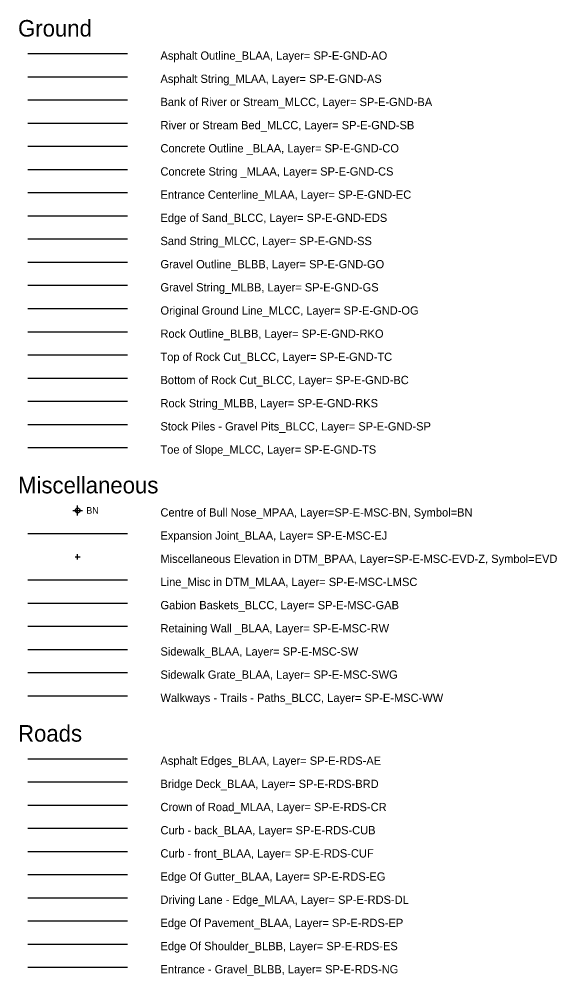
# Model space of a CAD drawing. Extents: x 500528 to 502626, y 4210261 to 4212624.
# Drawn here: x 501883.9 to 502046.2, y 4212035 to 4212324 of the extents above; entities that cross this region are included whole.
import ezdxf

# ---------------------------------------------------------------- set-up
doc = ezdxf.new("R2010")
doc.units = 0
for name, color, linetype in [('Default', 7, 'Continuous'), ('SP-E-GND-AO', 7, 'Continuous'), ('SP-E-GND-AS', 7, 'Continuous'), ('SP-E-GND-BA', 7, 'Continuous'), ('SP-E-GND-BC', 7, 'Continuous'), ('SP-E-GND-CO', 7, 'Continuous'), ('SP-E-GND-CS', 7, 'Continuous'), ('SP-E-GND-EC', 7, 'Continuous'), ('SP-E-GND-EDS', 7, 'Continuous'), ('SP-E-GND-GO', 7, 'Continuous'), ('SP-E-GND-GS', 7, 'Continuous'), ('SP-E-GND-OG', 7, 'Continuous'), ('SP-E-GND-RKO', 7, 'Continuous'), ('SP-E-GND-RKS', 7, 'Continuous'), ('SP-E-GND-SB', 7, 'Continuous'), ('SP-E-GND-SP', 7, 'Continuous'), ('SP-E-GND-SS', 7, 'Continuous'), ('SP-E-GND-TC', 7, 'Continuous'), ('SP-E-GND-TS', 7, 'Continuous'), ('SP-E-MSC-BN', 7, 'Continuous'), ('SP-E-MSC-EJ', 7, 'Continuous'), ('SP-E-MSC-EVD-Z', 7, 'Continuous'), ('SP-E-MSC-GAB', 7, 'Continuous'), ('SP-E-MSC-LMSC', 7, 'Continuous'), ('SP-E-MSC-RW', 7, 'Continuous'), ('SP-E-MSC-SW', 7, 'Continuous'), ('SP-E-MSC-SWG', 7, 'Continuous'), ('SP-E-MSC-T', 7, 'Continuous'), ('SP-E-MSC-WW', 7, 'Continuous'), ('SP-E-RDS-AE', 7, 'Continuous'), ('SP-E-RDS-BRD', 7, 'Continuous'), ('SP-E-RDS-CR', 7, 'Continuous'), ('SP-E-RDS-CUB', 7, 'Continuous'), ('SP-E-RDS-CUF', 7, 'Continuous'), ('SP-E-RDS-DL', 7, 'Continuous'), ('SP-E-RDS-EG', 7, 'Continuous'), ('SP-E-RDS-EP', 7, 'Continuous'), ('SP-E-RDS-ES', 7, 'Continuous'), ('SP-E-RDS-NG', 7, 'Continuous')]:
    doc.layers.add(name, color=color, linetype=linetype)

# ---------------------------------------------------------------- blocks, each defined once
blk = doc.blocks.new('POINT_DISPLAY')
at = {"layer": 'Default'}
blk.add_line((0, 0), (0, 0), dxfattribs=at)
blk = doc.blocks.new('BN')
at = {"layer": 'SP-E-MSC-T'}
for points in [[(-0.15, 0), (0.15, 0)], [(0, -0.15), (0, 0.15)]]:
    blk.add_lwpolyline(points, dxfattribs=at)
blk.add_circle((0, 0), 0.075, dxfattribs=at)
at = {"layer": 'SP-E-MSC-BN'}
blk.add_blockref('POINT_DISPLAY', (0, 0), dxfattribs=at)
at = {"layer": 'SP-E-MSC-T'}
blk.add_text('BN', height=0.2, dxfattribs=at).set_placement((0.262, -0.1))
blk = doc.blocks.new('EVD')
at = {"layer": 'SP-E-MSC-T'}
for points in [[(-0.08, 0), (0.08, 0)], [(0, -0.08), (0, 0.08)]]:
    blk.add_lwpolyline(points, dxfattribs=at)
at = {"layer": 'SP-E-MSC-EVD-Z'}
blk.add_blockref('POINT_DISPLAY', (0, 0), dxfattribs=at)

msp = doc.modelspace()

# ---------------------------------------------------------------- linework, layer by layer
at = {"layer": 'SP-E-GND-AO'}
msp.add_line((501886.55, 4212313.59), (501916.55, 4212313.59), dxfattribs=at)
at = {"layer": 'SP-E-GND-AS'}
msp.add_line((501886.55, 4212306.59), (501916.55, 4212306.59), dxfattribs=at)
at = {"layer": 'SP-E-GND-BA'}
msp.add_line((501886.55, 4212299.59), (501916.55, 4212299.59), dxfattribs=at)
at = {"layer": 'SP-E-GND-BC'}
msp.add_line((501886.55, 4212215.59), (501916.55, 4212215.59), dxfattribs=at)
at = {"layer": 'SP-E-GND-CO'}
msp.add_line((501886.55, 4212285.59), (501916.55, 4212285.59), dxfattribs=at)
at = {"layer": 'SP-E-GND-CS'}
msp.add_line((501886.55, 4212278.59), (501916.55, 4212278.59), dxfattribs=at)
at = {"layer": 'SP-E-GND-EC'}
msp.add_line((501886.55, 4212271.59), (501916.55, 4212271.59), dxfattribs=at)
at = {"layer": 'SP-E-GND-EDS'}
msp.add_line((501886.55, 4212264.59), (501916.55, 4212264.59), dxfattribs=at)
at = {"layer": 'SP-E-GND-GO'}
msp.add_line((501886.55, 4212250.59), (501916.55, 4212250.59), dxfattribs=at)
at = {"layer": 'SP-E-GND-GS'}
msp.add_line((501886.55, 4212243.59), (501916.55, 4212243.59), dxfattribs=at)
at = {"layer": 'SP-E-GND-OG'}
msp.add_line((501886.55, 4212236.59), (501916.55, 4212236.59), dxfattribs=at)
at = {"layer": 'SP-E-GND-RKO'}
msp.add_line((501886.55, 4212229.59), (501916.55, 4212229.59), dxfattribs=at)
at = {"layer": 'SP-E-GND-RKS'}
msp.add_line((501886.55, 4212208.59), (501916.55, 4212208.59), dxfattribs=at)
at = {"layer": 'SP-E-GND-SB'}
msp.add_line((501886.55, 4212292.59), (501916.55, 4212292.59), dxfattribs=at)
at = {"layer": 'SP-E-GND-SP'}
msp.add_line((501886.55, 4212201.59), (501916.55, 4212201.59), dxfattribs=at)
at = {"layer": 'SP-E-GND-SS'}
msp.add_line((501886.55, 4212257.59), (501916.55, 4212257.59), dxfattribs=at)
at = {"layer": 'SP-E-GND-TC'}
msp.add_line((501886.55, 4212222.59), (501916.55, 4212222.59), dxfattribs=at)
at = {"layer": 'SP-E-GND-TS'}
msp.add_line((501886.55, 4212194.59), (501916.55, 4212194.59), dxfattribs=at)
at = {"layer": 'SP-E-MSC-EJ'}
msp.add_line((501886.55, 4212168.59), (501916.55, 4212168.59), dxfattribs=at)
at = {"layer": 'SP-E-MSC-GAB'}
msp.add_line((501886.55, 4212147.59), (501916.55, 4212147.59), dxfattribs=at)
at = {"layer": 'SP-E-MSC-LMSC'}
msp.add_line((501886.55, 4212154.59), (501916.55, 4212154.59), dxfattribs=at)
at = {"layer": 'SP-E-MSC-RW'}
msp.add_line((501886.55, 4212140.59), (501916.55, 4212140.59), dxfattribs=at)
at = {"layer": 'SP-E-MSC-SW'}
msp.add_line((501886.55, 4212133.59), (501916.55, 4212133.59), dxfattribs=at)
at = {"layer": 'SP-E-MSC-SWG'}
msp.add_line((501886.55, 4212126.59), (501916.55, 4212126.59), dxfattribs=at)
at = {"layer": 'SP-E-MSC-WW'}
msp.add_line((501886.55, 4212119.59), (501916.55, 4212119.59), dxfattribs=at)
at = {"layer": 'SP-E-RDS-AE'}
msp.add_line((501886.55, 4212100.59), (501916.55, 4212100.59), dxfattribs=at)
at = {"layer": 'SP-E-RDS-BRD'}
msp.add_line((501886.55, 4212093.59), (501916.55, 4212093.59), dxfattribs=at)
at = {"layer": 'SP-E-RDS-CR'}
msp.add_line((501886.55, 4212086.59), (501916.55, 4212086.59), dxfattribs=at)
at = {"layer": 'SP-E-RDS-CUB'}
msp.add_line((501886.55, 4212079.59), (501916.55, 4212079.59), dxfattribs=at)
at = {"layer": 'SP-E-RDS-CUF'}
msp.add_line((501886.55, 4212072.59), (501916.55, 4212072.59), dxfattribs=at)
at = {"layer": 'SP-E-RDS-DL'}
msp.add_line((501886.55, 4212058.59), (501916.55, 4212058.59), dxfattribs=at)
at = {"layer": 'SP-E-RDS-EG'}
msp.add_line((501886.55, 4212065.59), (501916.55, 4212065.59), dxfattribs=at)
at = {"layer": 'SP-E-RDS-EP'}
msp.add_line((501886.55, 4212051.59), (501916.55, 4212051.59), dxfattribs=at)
at = {"layer": 'SP-E-RDS-ES'}
msp.add_line((501886.55, 4212044.59), (501916.55, 4212044.59), dxfattribs=at)
at = {"layer": 'SP-E-RDS-NG'}
msp.add_line((501886.55, 4212037.59), (501916.55, 4212037.59), dxfattribs=at)

# ---------------------------------------------------------------- block references
at = {"layer": 'SP-E-MSC-BN', "xscale": 10, "yscale": 10}
msp.add_blockref('BN', (501901.55, 4212175.59), dxfattribs=at)
at = {"layer": 'SP-E-MSC-EVD-Z', "xscale": 10, "yscale": 10}
msp.add_blockref('EVD', (501901.55, 4212161.59), dxfattribs=at)

# ---------------------------------------------------------------- texts
at = {"layer": 'Default'}
for s, p in [('Ground ', (501883.55, 4212318.74)), ('Miscellaneous ', (501883.55, 4212180.74)), ('Roads ', (501883.55, 4212105.74))]:
    msp.add_text(s, height=5, dxfattribs=at).set_placement(p)
at = {"layer": 'SP-E-GND-AO'}
msp.add_text('Asphalt Outline_BLAA, Layer= SP-E-GND-AO ', height=2.5, dxfattribs=at).set_placement((501926.55, 4212311.74))
at = {"layer": 'SP-E-GND-AS'}
msp.add_text('Asphalt String_MLAA, Layer= SP-E-GND-AS ', height=2.5, dxfattribs=at).set_placement((501926.55, 4212304.74))
at = {"layer": 'SP-E-GND-BA'}
msp.add_text('Bank of River or Stream_MLCC, Layer= SP-E-GND-BA ', height=2.5, dxfattribs=at).set_placement((501926.55, 4212297.74))
at = {"layer": 'SP-E-GND-BC'}
msp.add_text('Bottom of Rock Cut_BLCC, Layer= SP-E-GND-BC ', height=2.5, dxfattribs=at).set_placement((501926.55, 4212213.74))
at = {"layer": 'SP-E-GND-CO'}
msp.add_text('Concrete Outline _BLAA, Layer= SP-E-GND-CO ', height=2.5, dxfattribs=at).set_placement((501926.55, 4212283.74))
at = {"layer": 'SP-E-GND-CS'}
msp.add_text('Concrete String _MLAA, Layer= SP-E-GND-CS ', height=2.5, dxfattribs=at).set_placement((501926.55, 4212276.74))
at = {"layer": 'SP-E-GND-EC'}
msp.add_text('Entrance Centerline_MLAA, Layer= SP-E-GND-EC ', height=2.5, dxfattribs=at).set_placement((501926.55, 4212269.74))
at = {"layer": 'SP-E-GND-EDS'}
msp.add_text('Edge of Sand_BLCC, Layer= SP-E-GND-EDS ', height=2.5, dxfattribs=at).set_placement((501926.55, 4212262.74))
at = {"layer": 'SP-E-GND-GO'}
msp.add_text('Gravel Outline_BLBB, Layer= SP-E-GND-GO ', height=2.5, dxfattribs=at).set_placement((501926.55, 4212248.74))
at = {"layer": 'SP-E-GND-GS'}
msp.add_text('Gravel String_MLBB, Layer= SP-E-GND-GS ', height=2.5, dxfattribs=at).set_placement((501926.55, 4212241.74))
at = {"layer": 'SP-E-GND-OG'}
msp.add_text('Original Ground Line_MLCC, Layer= SP-E-GND-OG ', height=2.5, dxfattribs=at).set_placement((501926.55, 4212234.74))
at = {"layer": 'SP-E-GND-RKO'}
msp.add_text('Rock Outline_BLBB, Layer= SP-E-GND-RKO ', height=2.5, dxfattribs=at).set_placement((501926.55, 4212227.74))
at = {"layer": 'SP-E-GND-RKS'}
msp.add_text('Rock String_MLBB, Layer= SP-E-GND-RKS ', height=2.5, dxfattribs=at).set_placement((501926.55, 4212206.74))
at = {"layer": 'SP-E-GND-SB'}
msp.add_text('River or Stream Bed_MLCC, Layer= SP-E-GND-SB ', height=2.5, dxfattribs=at).set_placement((501926.55, 4212290.74))
at = {"layer": 'SP-E-GND-SP'}
msp.add_text('Stock Piles - Gravel Pits_BLCC, Layer= SP-E-GND-SP ', height=2.5, dxfattribs=at).set_placement((501926.55, 4212199.74))
at = {"layer": 'SP-E-GND-SS'}
msp.add_text('Sand String_MLCC, Layer= SP-E-GND-SS ', height=2.5, dxfattribs=at).set_placement((501926.55, 4212255.74))
at = {"layer": 'SP-E-GND-TC'}
msp.add_text('Top of Rock Cut_BLCC, Layer= SP-E-GND-TC ', height=2.5, dxfattribs=at).set_placement((501926.55, 4212220.74))
at = {"layer": 'SP-E-GND-TS'}
msp.add_text('Toe of Slope_MLCC, Layer= SP-E-GND-TS ', height=2.5, dxfattribs=at).set_placement((501926.55, 4212192.74))
at = {"layer": 'SP-E-MSC-BN'}
msp.add_text('Centre of Bull Nose_MPAA, Layer=SP-E-MSC-BN, Symbol=BN ', height=2.5, dxfattribs=at).set_placement((501926.55, 4212173.74))
at = {"layer": 'SP-E-MSC-EJ'}
msp.add_text('Expansion Joint_BLAA, Layer= SP-E-MSC-EJ ', height=2.5, dxfattribs=at).set_placement((501926.55, 4212166.74))
at = {"layer": 'SP-E-MSC-EVD-Z'}
msp.add_text('Miscellaneous Elevation in DTM_BPAA, Layer=SP-E-MSC-EVD-Z, Symbol=EVD ', height=2.5, dxfattribs=at).set_placement((501926.55, 4212159.74))
at = {"layer": 'SP-E-MSC-GAB'}
msp.add_text('Gabion Baskets_BLCC, Layer= SP-E-MSC-GAB ', height=2.5, dxfattribs=at).set_placement((501926.55, 4212145.74))
at = {"layer": 'SP-E-MSC-LMSC'}
msp.add_text('Line_Misc in DTM_MLAA, Layer= SP-E-MSC-LMSC ', height=2.5, dxfattribs=at).set_placement((501926.55, 4212152.74))
at = {"layer": 'SP-E-MSC-RW'}
msp.add_text('Retaining Wall _BLAA, Layer= SP-E-MSC-RW ', height=2.5, dxfattribs=at).set_placement((501926.55, 4212138.74))
at = {"layer": 'SP-E-MSC-SW'}
msp.add_text('Sidewalk_BLAA, Layer= SP-E-MSC-SW ', height=2.5, dxfattribs=at).set_placement((501926.55, 4212131.74))
at = {"layer": 'SP-E-MSC-SWG'}
msp.add_text('Sidewalk Grate_BLAA, Layer= SP-E-MSC-SWG ', height=2.5, dxfattribs=at).set_placement((501926.55, 4212124.74))
at = {"layer": 'SP-E-MSC-WW'}
msp.add_text('Walkways - Trails - Paths_BLCC, Layer= SP-E-MSC-WW ', height=2.5, dxfattribs=at).set_placement((501926.55, 4212117.74))
at = {"layer": 'SP-E-RDS-AE'}
msp.add_text('Asphalt Edges_BLAA, Layer= SP-E-RDS-AE ', height=2.5, dxfattribs=at).set_placement((501926.55, 4212098.74))
at = {"layer": 'SP-E-RDS-BRD'}
msp.add_text('Bridge Deck_BLAA, Layer= SP-E-RDS-BRD ', height=2.5, dxfattribs=at).set_placement((501926.55, 4212091.74))
at = {"layer": 'SP-E-RDS-CR'}
msp.add_text('Crown of Road_MLAA, Layer= SP-E-RDS-CR ', height=2.5, dxfattribs=at).set_placement((501926.55, 4212084.74))
at = {"layer": 'SP-E-RDS-CUB'}
msp.add_text('Curb - back_BLAA, Layer= SP-E-RDS-CUB ', height=2.5, dxfattribs=at).set_placement((501926.55, 4212077.74))
at = {"layer": 'SP-E-RDS-CUF'}
msp.add_text('Curb - front_BLAA, Layer= SP-E-RDS-CUF ', height=2.5, dxfattribs=at).set_placement((501926.55, 4212070.74))
at = {"layer": 'SP-E-RDS-DL'}
msp.add_text('Driving Lane - Edge_MLAA, Layer= SP-E-RDS-DL ', height=2.5, dxfattribs=at).set_placement((501926.55, 4212056.74))
at = {"layer": 'SP-E-RDS-EG'}
msp.add_text('Edge Of Gutter_BLAA, Layer= SP-E-RDS-EG ', height=2.5, dxfattribs=at).set_placement((501926.55, 4212063.74))
at = {"layer": 'SP-E-RDS-EP'}
msp.add_text('Edge Of Pavement_BLAA, Layer= SP-E-RDS-EP ', height=2.5, dxfattribs=at).set_placement((501926.55, 4212049.74))
at = {"layer": 'SP-E-RDS-ES'}
msp.add_text('Edge Of Shoulder_BLBB, Layer= SP-E-RDS-ES ', height=2.5, dxfattribs=at).set_placement((501926.55, 4212042.74))
at = {"layer": 'SP-E-RDS-NG'}
msp.add_text('Entrance - Gravel_BLBB, Layer= SP-E-RDS-NG ', height=2.5, dxfattribs=at).set_placement((501926.55, 4212035.74))

doc.saveas('drawing.dxf')
